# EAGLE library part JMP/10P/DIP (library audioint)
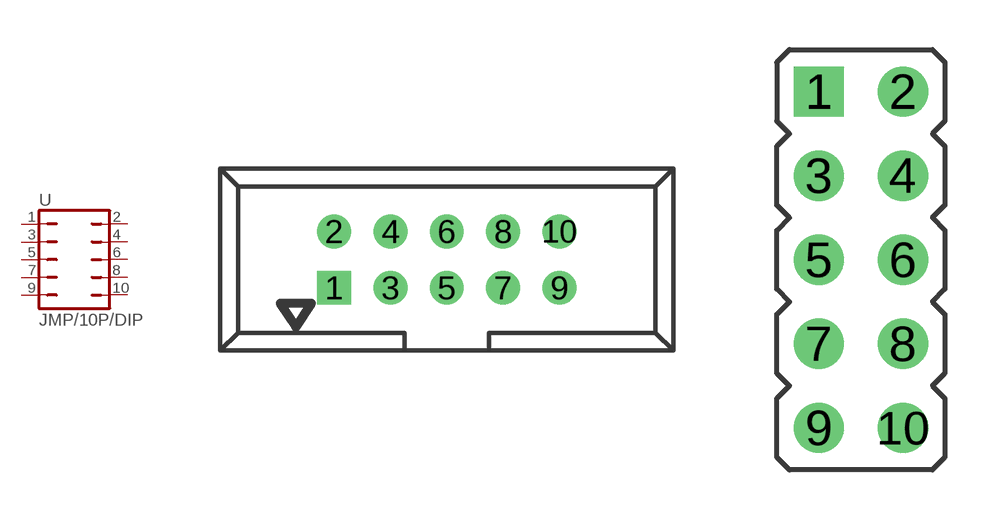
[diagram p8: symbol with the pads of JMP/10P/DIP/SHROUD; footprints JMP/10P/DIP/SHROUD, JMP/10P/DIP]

Designator prefix -

## JMP/10P/DIP  [JMP/10P/DIP/SHROUD]
1  1  pas
2  2  pas
3  3  pas
4  4  pas
5  5  pas
6  6  pas
7  7  pas
8  8  pas
9  9  pas
10  10  pas

## JMP/10P/DIPHEADER  [JMP/10P/DIP]
Pads as for JMP/10P/DIP/SHROUD

## Footprint JMP/10P/DIP/SHROUD (pad centres in mm)
drill 0.914 pad 1.524 square: 1 -5.08,-1.27
drill 0.914 pad 1.524 round: 2 -5.08,1.27; 3 -2.54,-1.27; 4 -2.54,1.27; 5 0,-1.27; 6 0,1.27; 7 2.54,-1.27; 8 2.54,1.27; 9 5.08,-1.27; 10 5.08,1.27

## Footprint JMP/10P/DIP (pad centres in mm)
drill 0.914 pad 1.524 square: 1 -1.27,5.08
drill 0.914 pad 1.524 round: 2 1.27,5.08; 3 -1.27,2.54; 4 1.27,2.54; 5 -1.27,0; 6 1.27,0; 7 -1.27,-2.54; 8 1.27,-2.54; 9 -1.27,-5.08; 10 1.27,-5.08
